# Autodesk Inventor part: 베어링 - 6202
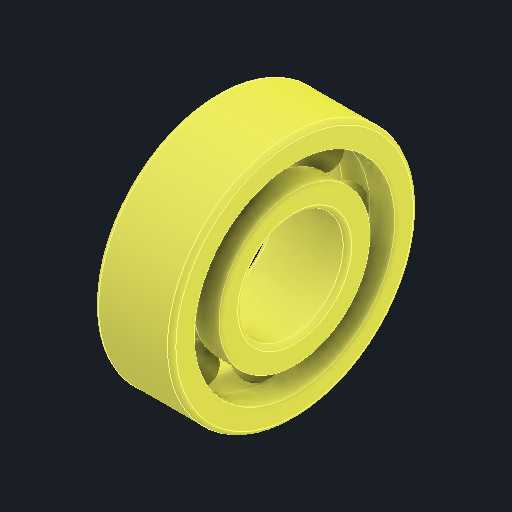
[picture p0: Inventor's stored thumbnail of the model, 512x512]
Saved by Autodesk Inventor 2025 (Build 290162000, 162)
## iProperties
Created: 2025-08
Part Number: 베어링 - 6202
Material: 강, 연강
Description: 깊은 그루브 볼 베어링
Document SubType Name: Modeling
Designer: infra10
Density: 7.86 g/cm^3
Appearance: 기본값
Author: jhkim
Sending System: Autodesk Inventor 2026
Preprocessor: ST-DEVELOPER v20.1
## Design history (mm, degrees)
feature "Solid1"
feature "Solid1:1"
feature "Solid1:2"
feature "Solid1:3"
feature "Solid1:4"
feature "Solid1:5"
feature "Solid1:6"
feature "Solid1:7"
feature "Solid1:8"
feature "Solid1:9"
node "솔리드1"
node "솔리드2"
node "솔리드3"
node "솔리드4"
node "솔리드5"
node "솔리드6"
node "솔리드7"
node "솔리드8"
node "솔리드9"
node "솔리드10"
